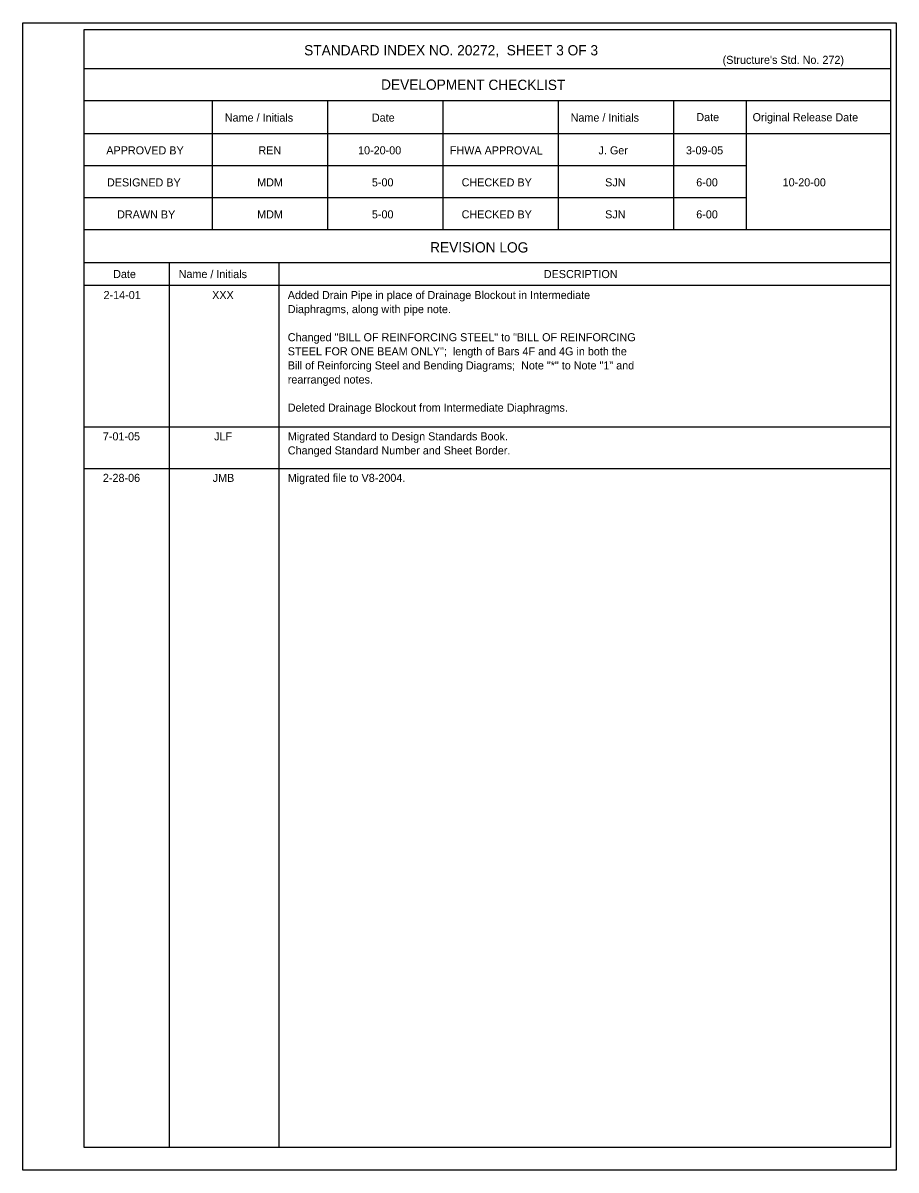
# Model space of a CAD drawing. Extents: x 120693.4 to 120747.1, y 120647.1 to 120670.1.
# Drawn here: x 120730.7 to 120747.06, y 120647.09 to 120668.59 of the extents above; entities that cross this region are included whole.
import ezdxf

# ---------------------------------------------------------------- set-up
doc = ezdxf.new("R2010")
doc.units = 0
for name, color, linetype in [('Border', 7, 'Continuous'), ('Dimension', 7, 'Continuous'), ('PlotBorder_dp', 7, 'Continuous'), ('TextStructures', 7, 'Continuous')]:
    doc.layers.add(name, color=color, linetype=linetype)

msp = doc.modelspace()

# ---------------------------------------------------------------- linework, layer by layer
at = {"layer": 'Border'}
for p, q in [((120746.956, 120667.737), (120731.846, 120667.737)), ((120746.956, 120667.137), (120731.846, 120667.137)), ((120734.246, 120667.137), (120734.246, 120664.716)), ((120736.406, 120667.137), (120736.406, 120664.716)), ((120738.566, 120667.137), (120738.566, 120664.716)), ((120740.726, 120667.137), (120740.726, 120664.716)), ((120742.886, 120667.137), (120742.886, 120664.716)), ((120744.247, 120667.137), (120744.247, 120664.716)), ((120746.956, 120666.516), (120731.846, 120666.516)), ((120744.247, 120665.916), (120731.846, 120665.916)), ((120744.247, 120665.316), (120731.846, 120665.316)), ((120746.956, 120664.716), (120731.846, 120664.716)), ((120746.956, 120664.095), (120731.846, 120664.095)), ((120733.436, 120664.095), (120733.436, 120647.515)), ((120735.493, 120664.095), (120735.493, 120647.515)), ((120746.956, 120663.672), (120731.846, 120663.672))]:
    msp.add_line(p, q, dxfattribs=at)
msp.add_lwpolyline([(120731.846, 120668.472), (120746.956, 120668.472), (120746.956, 120647.515), (120731.846, 120647.515)], close=True, dxfattribs=at)
at = {"layer": 'Dimension'}
for p, q in [((120731.846, 120661.024), (120746.956, 120661.024)), ((120731.846, 120660.246), (120746.956, 120660.246))]:
    msp.add_line(p, q, dxfattribs=at)
at = {"layer": 'PlotBorder_dp'}
msp.add_line((120730.698, 120647.094), (120730.698, 120647.094), dxfattribs=at)
msp.add_lwpolyline([(120730.698, 120668.594), (120747.058, 120668.594), (120747.058, 120647.094), (120730.698, 120647.094)], close=True, dxfattribs=at)

# ---------------------------------------------------------------- texts
at = {"layer": 'TextStructures'}
for s, height, p in [('STANDARD INDEX NO. 20272,  SHEET 3 OF 3', 0.192, (120735.967, 120667.986)), ("(Structure's Std. No. 272)", 0.1512, (120743.808, 120667.827)), ('REN', 0.1512, (120735.11, 120666.131)), ('10-20-00', 0.1512, (120736.977, 120666.131)), ('J. Ger', 0.1512, (120741.483, 120666.131)), ('3-09-05', 0.1512, (120743.121, 120666.131)), ('MDM', 0.1512, (120735.086, 120665.531)), ('5-00', 0.1512, (120737.236, 120665.531)), ('SJN', 0.1512, (120741.607, 120665.531)), ('6-00', 0.1512, (120743.314, 120665.531)), ('10-20-00', 0.1512, (120744.933, 120665.531)), ('MDM', 0.1512, (120735.086, 120664.931)), ('5-00', 0.1512, (120737.236, 120664.931)), ('SJN', 0.1512, (120741.607, 120664.931)), ('6-00', 0.1512, (120743.314, 120664.931)), ('DESCRIPTION', 0.1512, (120740.458, 120663.812)), ('2-14-01', 0.1512, (120732.208, 120663.419)), ('XXX', 0.1512, (120734.243, 120663.419)), ('Added Drain Pipe in place of Drainage Blockout in Intermediate', 0.1512, (120735.66, 120663.419)), ('Diaphragms, along with pipe note.', 0.1512, (120735.66, 120663.155)), ('Changed "BILL OF REINFORCING STEEL" to "BILL OF REINFORCING', 0.1512, (120735.66, 120662.628)), ('STEEL FOR ONE BEAM ONLY";  length of Bars 4F and 4G in both the', 0.1512, (120735.66, 120662.364)), ('Bill of Reinforcing Steel and Bending Diagrams;  Note "*" to Note "1" and', 0.1512, (120735.66, 120662.1)), ('rearranged notes.', 0.1512, (120735.66, 120661.836)), ('Deleted Drainage Blockout from Intermediate Diaphragms.', 0.1512, (120735.66, 120661.309)), ('7-01-05', 0.1512, (120732.195, 120660.77)), ('JLF', 0.1512, (120734.281, 120660.77)), ('Migrated Standard to Design Standards Book.', 0.1512, (120735.661, 120660.77)), ('Changed Standard Number and Sheet Border.', 0.1512, (120735.661, 120660.507)), ('2-28-06', 0.1512, (120732.196, 120659.992)), ('JMB', 0.1512, (120734.253, 120659.992)), ('Migrated file to V8-2004.', 0.1512, (120735.66, 120659.992))]:
    msp.add_text(s, height=height, dxfattribs=at).set_placement(p)
for s, height, p in [('DEVELOPMENT CHECKLIST', 0.192, (120737.408, 120667.344)), ('Name / Initials', 0.1512, (120734.48, 120666.746)), ('Date', 0.1512, (120737.236, 120666.745)), ('Name / Initials', 0.1512, (120740.96, 120666.746)), ('Date', 0.1512, (120743.315, 120666.754)), ('Original Release Date', 0.1512, (120744.37, 120666.753)), ('APPROVED BY', 0.1512, (120732.26, 120666.132)), ('FHWA APPROVAL', 0.1512, (120738.697, 120666.132)), ('DESIGNED BY', 0.1512, (120732.272, 120665.531)), ('CHECKED BY', 0.1512, (120738.918, 120665.532)), ('DRAWN BY', 0.1512, (120732.462, 120664.931)), ('CHECKED BY', 0.1512, (120738.918, 120664.932)), ('REVISION LOG', 0.192, (120738.327, 120664.295)), ('Date', 0.1512, (120732.388, 120663.813)), ('Name / Initials', 0.1512, (120733.615, 120663.814))]:
    msp.add_text(s, height=height, rotation=359.8756, dxfattribs=at).set_placement(p)

doc.saveas('drawing.dxf')
